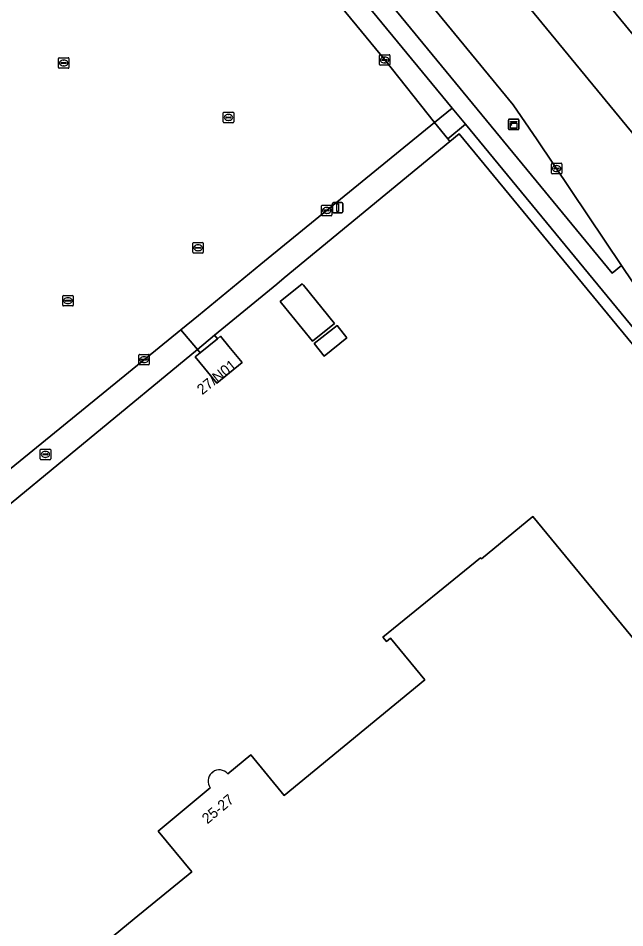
# Model space of a CAD drawing. Extents: x 156141 to 158132, y 385651 to 388333.
# Drawn here: x 157208.1 to 157265.8, y 386249.2 to 386335.6 of the extents above; entities that cross this region are included whole.
import ezdxf

# ---------------------------------------------------------------- set-up
doc = ezdxf.new("R2010")
doc.units = 0
for name, color, linetype in [('IMGEO_Berm_groen', 7, 'Continuous'), ('IMGEO_Brandkraan', 7, 'Continuous'), ('IMGEO_Erf', 7, 'Continuous'), ('IMGEO_Groenvoorziening', 7, 'Continuous'), ('IMGEO_Haag', 7, 'Continuous'), ('IMGEO_Hek', 7, 'Continuous'), ('IMGEO_Kast', 7, 'Continuous'), ('IMGEO_Kolk', 7, 'Continuous'), ('IMGEO_Lichtmast', 7, 'Continuous'), ('IMGEO_Pand', 7, 'Continuous'), ('IMGEO_Pand_nummerreeks', 7, 'Continuous'), ('IMGEO_Rijbaan_lokaal_gesloten', 7, 'Continuous'), ('IMGEO_Rioolput', 7, 'Continuous'), ('IMGEO_Voetpad_open', 7, 'Continuous')]:
    doc.layers.add(name, color=color, linetype=linetype)

msp = doc.modelspace()

# ---------------------------------------------------------------- linework, layer by layer
at = {"layer": 'IMGEO_Berm_groen'}
for points in [[(157205.755, 386407.826), (157203.781, 386410.196), (157199.193, 386406.39), (157201.153, 386404.033), (157327.942, 386250), (157336.115, 386240.102), (157337.285, 386238.671)], [(157342.288, 386241.546), (157341.401, 386242.711), (157335.682, 386250), (157205.755, 386407.826)], [(157211.154, 386376.22), (157264.546, 386311.336), (157265.451, 386312.065), (157257.428, 386324.032), (157255.15, 386327.344), (157194.1, 386401.515)]]:
    msp.add_lwpolyline(points, dxfattribs=at)
at = {"layer": 'IMGEO_Brandkraan'}
for p, q in [((157210.172, 386293.707), (157210.172, 386294.559)), ((157210.247, 386294.633), (157211.099, 386294.633)), ((157210.66, 386294.413), (157210.685, 386294.413)), ((157211.173, 386294.559), (157211.173, 386293.707)), ((157211.099, 386293.633), (157210.247, 386293.633)), ((157210.431, 386294.127), (157210.431, 386294.139)), ((157210.869, 386294.09), (157210.471, 386294.09)), ((157210.474, 386294.176), (157210.872, 386294.176)), ((157210.683, 386293.853), (157210.658, 386293.853)), ((157210.915, 386294.139), (157210.915, 386294.127))]:
    msp.add_line(p, q, dxfattribs=at)
for points in [[(157210.172, 386293.707), (157210.172, 386294.559)], [(157210.247, 386294.633), (157211.099, 386294.633)], [(157211.173, 386294.559), (157211.173, 386293.707)], [(157211.099, 386293.633), (157210.247, 386293.633)]]:
    msp.add_lwpolyline(points, dxfattribs=at)
for centre, radius, start, end in [((157210.249, 386294.557), 0.0765, 91.55205, 178.44795), ((157210.249, 386294.557), 0.0765, 91.55205, 178.44795), ((157211.097, 386294.557), 0.0765, 1.55205, 88.44795), ((157211.097, 386294.557), 0.0765, 1.55205, 88.44795), ((157210.249, 386293.709), 0.0765, 181.55205, 268.44795), ((157210.249, 386293.709), 0.0765, 181.55205, 268.44795), ((157210.471, 386294.136), 0.0403, 85.87752, 175.75265), ((157210.468, 386294.126), 0.0366, 178.93798, 274.71019), ((157210.872, 386294.133), 0.043, 264.86636, 352.45326), ((157210.876, 386294.138), 0.0386, 1.73085, 96.63898), ((157211.097, 386293.709), 0.0765, 271.55205, 358.44795), ((157211.097, 386293.709), 0.0765, 271.55205, 358.44795)]:
    msp.add_arc(centre, radius, start, end, dxfattribs=at)
for centre, major_axis, ratio, start_param, end_param in [((157210.659, 386294.133), (-0.387, 0.002), 0.722429, 4.712389, 7.853982), ((157210.684, 386294.133), (-0.39, 0.002), 0.717154, 1.570796, 4.712389)]:
    msp.add_ellipse(centre, major_axis=major_axis, ratio=ratio, start_param=start_param, end_param=end_param, dxfattribs=at)
at = {"layer": 'IMGEO_Erf'}
for points in [[(157223.541, 386305.983), (157225.229, 386307.333), (157231.137, 386312.191), (157231.851, 386312.773), (157247.676, 386325.673), (157242.926, 386331.607), (157204.09, 386378.741)], [(157213.671, 386179.31), (157318.008, 386237.675), (157310.24, 386250.894), (157308.881, 386253.009), (157305.737, 386257.034), (157297.068, 386267.539), (157250.016, 386324.597), (157249.125, 386323.863), (157233.385, 386310.904), (157232.673, 386310.318), (157226.757, 386305.447), (157227.019, 386305.124), (157227.309, 386305.361), (157228.122, 386304.37), (157229.365, 386302.857), (157226.965, 386300.89), (157224.909, 386303.4), (157225.394, 386303.796), (157225.13, 386304.108), (157163.286, 386253.19), (157161.441, 386255.415), (157161.905, 386255.778), (157223.541, 386305.983)], [(157252.024, 386284.317), (157252.119, 386284.201), (157257.025, 386288.239), (157288.502, 386250), (157288.753, 386249.695), (157266.104, 386236.815), (157262.283, 386243.437), (157254.077, 386236.659), (157255.229, 386235.26), (157246.303, 386227.923), (157245.155, 386229.365), (157210.228, 386200.571), (157189.567, 386225.684), (157219.124, 386250), (157224.577, 386254.486), (157221.379, 386258.33), (157226.345, 386262.461)], [(157228.013, 386263.798), (157230.205, 386265.602), (157233.383, 386261.742), (157246.732, 386272.73), (157243.491, 386276.668), (157243.105, 386276.35), (157242.755, 386276.774), (157252.024, 386284.317)], [(157226.478, 386263.873), (157226.574, 386263.953)]]:
    msp.add_lwpolyline(points, dxfattribs=at)
for points in [[(157233.128, 386308.491), (157232.999, 386308.65), (157235.084, 386310.349), (157235.204, 386310.201), (157238.154, 386306.582), (157236.069, 386304.883)], [(157238.407, 386306.377), (157239.339, 386305.198), (157237.159, 386303.475), (157236.227, 386304.654)]]:
    msp.add_lwpolyline(points, close=True, dxfattribs=at)
for centre, radius, start, end in [((157227.209, 386263.089), 1.072, 41.38761, 126.31671), ((157227.209, 386263.092), 1.07, 133.11872, 216.11935)]:
    msp.add_arc(centre, radius, start, end, dxfattribs=at)
at = {"layer": 'IMGEO_Groenvoorziening'}
msp.add_lwpolyline([(157204.09, 386378.741), (157242.926, 386331.607), (157247.676, 386325.673), (157249.344, 386327.032), (157209.826, 386374.969)], dxfattribs=at)
for points in [[(157250.614, 386325.491), (157248.932, 386324.105), (157249.125, 386323.863), (157250.016, 386324.597), (157297.068, 386267.539), (157305.737, 386257.034), (157308.881, 386253.009), (157310.24, 386250.894), (157318.008, 386237.675), (157319.091, 386238.264), (157310.849, 386252.423)], [(157223.541, 386305.983), (157161.905, 386255.778), (157161.441, 386255.415), (157163.286, 386253.19), (157225.13, 386304.108)]]:
    msp.add_lwpolyline(points, close=True, dxfattribs=at)
at = {"layer": 'IMGEO_Haag'}
msp.add_lwpolyline([(157223.541, 386305.983), (157161.905, 386255.778), (157161.441, 386255.415), (157163.286, 386253.19), (157225.13, 386304.108)], close=True, dxfattribs=at)
at = {"layer": 'IMGEO_Hek'}
for points in [[(157297.068, 386267.539), (157250.016, 386324.597), (157233.385, 386310.904)], [(157233.385, 386310.904), (157232.673, 386310.318)], [(157232.673, 386310.318), (157226.757, 386305.447)], [(157226.757, 386305.447), (157225.13, 386304.108)], [(157225.13, 386304.108), (157163.286, 386253.19)]]:
    msp.add_lwpolyline(points, dxfattribs=at)
at = {"layer": 'IMGEO_Kast'}
for p, q in [((157254.691, 386325.06), (157254.691, 386325.901)), ((157254.691, 386325.901), (157254.691, 386325.06)), ((157254.766, 386325.985), (157255.607, 386325.985)), ((157255.607, 386325.985), (157254.766, 386325.985)), ((157255.691, 386325.91), (157255.691, 386325.069)), ((157255.691, 386325.069), (157255.691, 386325.91)), ((157255.616, 386324.985), (157254.775, 386324.985)), ((157254.775, 386324.985), (157255.616, 386324.985))]:
    msp.add_line(p, q, dxfattribs=at)
for points in [[(157254.886, 386325.775), (157255.486, 386325.775), (157255.486, 386325.69), (157254.886, 386325.69), (157254.886, 386325.775)], [(157254.886, 386325.6), (157255.486, 386325.6), (157255.486, 386325.111), (157254.886, 386325.111), (157254.886, 386325.6)]]:
    msp.add_lwpolyline(points, dxfattribs=at)
msp.add_circle((157254.97, 386325.449), 0.0377, dxfattribs=at)
for centre, start, end in [((157254.769, 386325.907), 92.4484, 184.28452), ((157254.769, 386325.907), 92.4484, 184.28452), ((157255.613, 386325.907), 2.4484, 94.28452), ((157255.613, 386325.907), 2.4484, 94.28452), ((157254.769, 386325.063), 182.4484, 274.28452), ((157254.769, 386325.063), 182.4484, 274.28452), ((157255.613, 386325.063), 272.4484, 4.28452), ((157255.613, 386325.063), 272.4484, 4.28452)]:
    msp.add_arc(centre, 0.0779, start, end, dxfattribs=at)
at = {"layer": 'IMGEO_Kolk'}
for p, q in [((157211.911, 386330.892), (157211.911, 386331.744)), ((157211.986, 386331.818), (157212.838, 386331.818)), ((157212.399, 386331.598), (157212.424, 386331.598)), ((157212.912, 386331.744), (157212.912, 386330.892)), ((157242.425, 386331.181), (157242.425, 386332.033)), ((157242.5, 386332.107), (157243.352, 386332.107)), ((157242.684, 386331.601), (157242.684, 386331.613)), ((157243.122, 386331.564), (157242.724, 386331.564)), ((157242.727, 386331.65), (157243.125, 386331.65)), ((157242.913, 386331.887), (157242.938, 386331.887)), ((157243.168, 386331.613), (157243.168, 386331.601)), ((157243.426, 386332.033), (157243.426, 386331.181)), ((157212.838, 386330.818), (157211.986, 386330.818)), ((157212.17, 386331.312), (157212.17, 386331.324)), ((157212.608, 386331.275), (157212.21, 386331.275)), ((157212.213, 386331.361), (157212.611, 386331.361)), ((157212.422, 386331.038), (157212.397, 386331.038)), ((157212.654, 386331.324), (157212.654, 386331.312)), ((157243.352, 386331.107), (157242.5, 386331.107)), ((157242.936, 386331.327), (157242.911, 386331.327)), ((157227.574, 386325.716), (157227.574, 386326.568)), ((157227.649, 386326.642), (157228.501, 386326.642)), ((157228.062, 386326.422), (157228.087, 386326.422)), ((157228.575, 386326.568), (157228.575, 386325.716)), ((157228.501, 386325.642), (157227.649, 386325.642)), ((157227.833, 386326.136), (157227.833, 386326.148)), ((157228.271, 386326.099), (157227.873, 386326.099)), ((157227.876, 386326.185), (157228.274, 386326.185)), ((157228.085, 386325.862), (157228.06, 386325.862)), ((157228.317, 386326.148), (157228.317, 386326.136)), ((157258.775, 386320.865), (157258.775, 386321.717)), ((157258.85, 386321.791), (157259.702, 386321.791)), ((157259.034, 386321.285), (157259.034, 386321.297)), ((157259.472, 386321.248), (157259.074, 386321.248)), ((157259.077, 386321.334), (157259.475, 386321.334)), ((157259.263, 386321.571), (157259.288, 386321.571)), ((157259.518, 386321.297), (157259.518, 386321.285)), ((157259.776, 386321.717), (157259.776, 386320.865)), ((157259.702, 386320.791), (157258.85, 386320.791)), ((157259.286, 386321.011), (157259.261, 386321.011)), ((157236.915, 386316.884), (157236.915, 386317.736)), ((157236.99, 386317.81), (157237.842, 386317.81)), ((157237.916, 386317.736), (157237.916, 386316.884)), ((157237.842, 386316.81), (157236.99, 386316.81)), ((157237.174, 386317.304), (157237.174, 386317.316)), ((157237.612, 386317.267), (157237.214, 386317.267)), ((157237.217, 386317.353), (157237.615, 386317.353)), ((157237.426, 386317.03), (157237.401, 386317.03)), ((157237.403, 386317.59), (157237.428, 386317.59)), ((157237.658, 386317.316), (157237.658, 386317.304)), ((157212.315, 386308.308), (157212.315, 386309.16)), ((157212.39, 386309.234), (157213.242, 386309.234)), ((157212.803, 386309.014), (157212.828, 386309.014)), ((157213.316, 386309.16), (157213.316, 386308.308)), ((157213.242, 386308.234), (157212.39, 386308.234)), ((157212.574, 386308.728), (157212.574, 386308.74)), ((157213.012, 386308.691), (157212.614, 386308.691)), ((157212.617, 386308.777), (157213.015, 386308.777)), ((157212.826, 386308.454), (157212.801, 386308.454)), ((157213.058, 386308.74), (157213.058, 386308.728)), ((157219.548, 386302.712), (157219.548, 386303.564)), ((157219.623, 386303.638), (157220.475, 386303.638)), ((157219.807, 386303.132), (157219.807, 386303.144)), ((157220.245, 386303.095), (157219.847, 386303.095)), ((157219.85, 386303.181), (157220.248, 386303.181)), ((157220.036, 386303.418), (157220.061, 386303.418)), ((157220.291, 386303.144), (157220.291, 386303.132)), ((157220.549, 386303.564), (157220.549, 386302.712)), ((157220.475, 386302.638), (157219.623, 386302.638)), ((157220.059, 386302.858), (157220.034, 386302.858))]:
    msp.add_line(p, q, dxfattribs=at)
for points in [[(157211.911, 386330.892), (157211.911, 386331.744)], [(157211.986, 386331.818), (157212.838, 386331.818)], [(157212.912, 386331.744), (157212.912, 386330.892)], [(157242.425, 386331.181), (157242.425, 386332.033)], [(157242.5, 386332.107), (157243.352, 386332.107)], [(157243.426, 386332.033), (157243.426, 386331.181)], [(157212.838, 386330.818), (157211.986, 386330.818)], [(157243.352, 386331.107), (157242.5, 386331.107)], [(157227.574, 386325.716), (157227.574, 386326.568)], [(157227.649, 386326.642), (157228.501, 386326.642)], [(157228.575, 386326.568), (157228.575, 386325.716)], [(157228.501, 386325.642), (157227.649, 386325.642)], [(157258.775, 386320.865), (157258.775, 386321.717)], [(157258.85, 386321.791), (157259.702, 386321.791)], [(157259.776, 386321.717), (157259.776, 386320.865)], [(157259.702, 386320.791), (157258.85, 386320.791)], [(157236.915, 386316.884), (157236.915, 386317.736)], [(157236.99, 386317.81), (157237.842, 386317.81)], [(157237.916, 386317.736), (157237.916, 386316.884)], [(157237.842, 386316.81), (157236.99, 386316.81)], [(157212.315, 386308.308), (157212.315, 386309.16)], [(157212.39, 386309.234), (157213.242, 386309.234)], [(157213.316, 386309.16), (157213.316, 386308.308)], [(157213.242, 386308.234), (157212.39, 386308.234)], [(157219.548, 386302.712), (157219.548, 386303.564)], [(157219.623, 386303.638), (157220.475, 386303.638)], [(157220.549, 386303.564), (157220.549, 386302.712)], [(157220.475, 386302.638), (157219.623, 386302.638)]]:
    msp.add_lwpolyline(points, dxfattribs=at)
for centre, radius, start, end in [((157211.988, 386331.742), 0.0765, 91.55205, 178.44795), ((157211.988, 386331.742), 0.0765, 91.55205, 178.44795), ((157212.836, 386331.742), 0.0765, 1.55205, 88.44795), ((157212.836, 386331.742), 0.0765, 1.55205, 88.44795), ((157242.502, 386332.031), 0.0765, 91.55205, 178.44795), ((157242.502, 386332.031), 0.0765, 91.55205, 178.44795), ((157242.724, 386331.61), 0.0403, 85.87752, 175.75265), ((157242.721, 386331.6), 0.0366, 178.93798, 274.71019), ((157243.125, 386331.607), 0.043, 264.86636, 352.45326), ((157243.129, 386331.612), 0.0386, 1.73085, 96.63898), ((157243.35, 386332.031), 0.0765, 1.55205, 88.44795), ((157243.35, 386332.031), 0.0765, 1.55205, 88.44795), ((157211.988, 386330.894), 0.0765, 181.55205, 268.44795), ((157211.988, 386330.894), 0.0765, 181.55205, 268.44795), ((157212.21, 386331.321), 0.0403, 85.87752, 175.75265), ((157212.207, 386331.311), 0.0366, 178.93798, 274.71019), ((157212.611, 386331.318), 0.043, 264.86636, 352.45326), ((157212.615, 386331.323), 0.0386, 1.73085, 96.63898), ((157212.836, 386330.894), 0.0765, 271.55205, 358.44795), ((157212.836, 386330.894), 0.0765, 271.55205, 358.44795), ((157242.502, 386331.183), 0.0765, 181.55205, 268.44795), ((157242.502, 386331.183), 0.0765, 181.55205, 268.44795), ((157243.35, 386331.183), 0.0765, 271.55205, 358.44795), ((157243.35, 386331.183), 0.0765, 271.55205, 358.44795), ((157227.651, 386326.566), 0.0765, 91.55205, 178.44795), ((157227.651, 386326.566), 0.0765, 91.55205, 178.44795), ((157228.499, 386326.566), 0.0765, 1.55205, 88.44795), ((157228.499, 386326.566), 0.0765, 1.55205, 88.44795), ((157227.651, 386325.718), 0.0765, 181.55205, 268.44795), ((157227.651, 386325.718), 0.0765, 181.55205, 268.44795), ((157227.873, 386326.145), 0.0403, 85.87752, 175.75265), ((157227.87, 386326.135), 0.0366, 178.93798, 274.71019), ((157228.274, 386326.142), 0.043, 264.86636, 352.45326), ((157228.278, 386326.147), 0.0386, 1.73085, 96.63898), ((157228.499, 386325.718), 0.0765, 271.55205, 358.44795), ((157228.499, 386325.718), 0.0765, 271.55205, 358.44795), ((157258.852, 386321.715), 0.0765, 91.55205, 178.44795), ((157258.852, 386321.715), 0.0765, 91.55205, 178.44795), ((157259.074, 386321.294), 0.0403, 85.87752, 175.75265), ((157259.071, 386321.284), 0.0366, 178.93798, 274.71019), ((157259.475, 386321.291), 0.043, 264.86636, 352.45326), ((157259.479, 386321.296), 0.0386, 1.73085, 96.63898), ((157259.7, 386321.715), 0.0765, 1.55205, 88.44795), ((157259.7, 386321.715), 0.0765, 1.55205, 88.44795), ((157258.852, 386320.867), 0.0765, 181.55205, 268.44795), ((157258.852, 386320.867), 0.0765, 181.55205, 268.44795), ((157259.7, 386320.867), 0.0765, 271.55205, 358.44795), ((157259.7, 386320.867), 0.0765, 271.55205, 358.44795), ((157236.992, 386317.734), 0.0765, 91.55205, 178.44795), ((157236.992, 386317.734), 0.0765, 91.55205, 178.44795), ((157237.84, 386317.734), 0.0765, 1.55205, 88.44795), ((157237.84, 386317.734), 0.0765, 1.55205, 88.44795), ((157236.992, 386316.886), 0.0765, 181.55205, 268.44795), ((157236.992, 386316.886), 0.0765, 181.55205, 268.44795), ((157237.214, 386317.313), 0.0403, 85.87752, 175.75265), ((157237.211, 386317.303), 0.0366, 178.93798, 274.71019), ((157237.615, 386317.31), 0.043, 264.86636, 352.45326), ((157237.619, 386317.315), 0.0386, 1.73085, 96.63898), ((157237.84, 386316.886), 0.0765, 271.55205, 358.44795), ((157237.84, 386316.886), 0.0765, 271.55205, 358.44795), ((157212.392, 386309.158), 0.0765, 91.55205, 178.44795), ((157212.392, 386309.158), 0.0765, 91.55205, 178.44795), ((157213.24, 386309.158), 0.0765, 1.55205, 88.44795), ((157213.24, 386309.158), 0.0765, 1.55205, 88.44795), ((157212.392, 386308.31), 0.0765, 181.55205, 268.44795), ((157212.392, 386308.31), 0.0765, 181.55205, 268.44795), ((157212.614, 386308.737), 0.0403, 85.87752, 175.75265), ((157212.611, 386308.727), 0.0366, 178.93798, 274.71019), ((157213.015, 386308.734), 0.043, 264.86636, 352.45326), ((157213.019, 386308.739), 0.0386, 1.73085, 96.63898), ((157213.24, 386308.31), 0.0765, 271.55205, 358.44795), ((157213.24, 386308.31), 0.0765, 271.55205, 358.44795), ((157219.625, 386303.562), 0.0765, 91.55205, 178.44795), ((157219.625, 386303.562), 0.0765, 91.55205, 178.44795), ((157219.847, 386303.141), 0.0403, 85.87752, 175.75265), ((157219.844, 386303.131), 0.0366, 178.93798, 274.71019), ((157220.248, 386303.138), 0.043, 264.86636, 352.45326), ((157220.252, 386303.143), 0.0386, 1.73085, 96.63898), ((157220.473, 386303.562), 0.0765, 1.55205, 88.44795), ((157220.473, 386303.562), 0.0765, 1.55205, 88.44795), ((157219.625, 386302.714), 0.0765, 181.55205, 268.44795), ((157219.625, 386302.714), 0.0765, 181.55205, 268.44795), ((157220.473, 386302.714), 0.0765, 271.55205, 358.44795), ((157220.473, 386302.714), 0.0765, 271.55205, 358.44795)]:
    msp.add_arc(centre, radius, start, end, dxfattribs=at)
for centre, major_axis, ratio, start_param, end_param in [((157212.398, 386331.318), (-0.387, 0.002), 0.722429, 4.712389, 7.853982), ((157212.423, 386331.318), (-0.39, 0.002), 0.717154, 1.570796, 4.712389), ((157242.912, 386331.607), (-0.387, 0.002), 0.722429, 4.712389, 7.853982), ((157242.937, 386331.607), (-0.39, 0.002), 0.717154, 1.570796, 4.712389), ((157228.061, 386326.142), (-0.387, 0.002), 0.722429, 4.712389, 7.853982), ((157228.086, 386326.142), (-0.39, 0.002), 0.717154, 1.570796, 4.712389), ((157259.262, 386321.291), (-0.387, 0.002), 0.722429, 4.712389, 7.853982), ((157259.287, 386321.291), (-0.39, 0.002), 0.717154, 1.570796, 4.712389), ((157237.402, 386317.31), (-0.387, 0.002), 0.722429, 4.712389, 7.853982), ((157237.427, 386317.31), (-0.39, 0.002), 0.717154, 1.570796, 4.712389), ((157212.802, 386308.734), (-0.387, 0.002), 0.722429, 4.712389, 7.853982), ((157212.827, 386308.734), (-0.39, 0.002), 0.717154, 1.570796, 4.712389), ((157220.035, 386303.138), (-0.387, 0.002), 0.722429, 4.712389, 7.853982), ((157220.06, 386303.138), (-0.39, 0.002), 0.717154, 1.570796, 4.712389)]:
    msp.add_ellipse(centre, major_axis=major_axis, ratio=ratio, start_param=start_param, end_param=end_param, dxfattribs=at)
at = {"layer": 'IMGEO_Lichtmast'}
for p, q in [((157237.953, 386317.178), (157237.953, 386317.978)), ((157237.953, 386317.978), (157237.953, 386317.178)), ((157238.053, 386318.078), (157238.843, 386318.078)), ((157238.843, 386318.078), (157238.053, 386318.078)), ((157238.943, 386317.978), (157238.943, 386317.178)), ((157238.943, 386317.178), (157238.943, 386317.978)), ((157238.843, 386317.078), (157238.053, 386317.078)), ((157238.053, 386317.078), (157238.843, 386317.078))]:
    msp.add_line(p, q, dxfattribs=at)
msp.add_lwpolyline([(157238.373, 386317.953), (157238.523, 386317.953), (157238.523, 386317.203), (157238.373, 386317.203), (157238.373, 386317.953)], dxfattribs=at)
for centre, start, end in [((157238.053, 386317.978), 90, 180), ((157238.053, 386317.978), 90, 180), ((157238.843, 386317.978), 0, 90), ((157238.843, 386317.978), 360, 90), ((157238.053, 386317.178), 180, 270), ((157238.053, 386317.178), 180, 270), ((157238.843, 386317.178), 270, 0), ((157238.843, 386317.178), 270, 0)]:
    msp.add_arc(centre, 0.1, start, end, dxfattribs=at)
at = {"layer": 'IMGEO_Pand'}
for points in [[(157233.128, 386308.491), (157236.069, 386304.883), (157238.154, 386306.582), (157235.204, 386310.201), (157235.084, 386310.349), (157232.999, 386308.65)], [(157239.339, 386305.198), (157238.407, 386306.377), (157236.227, 386304.654), (157237.159, 386303.475)], [(157227.309, 386305.361), (157227.019, 386305.124), (157225.394, 386303.796), (157224.909, 386303.4), (157226.965, 386300.89), (157229.365, 386302.857), (157228.122, 386304.37)]]:
    msp.add_lwpolyline(points, close=True, dxfattribs=at)
for points in [[(157288.753, 386249.695), (157288.502, 386250), (157257.025, 386288.239), (157252.119, 386284.201), (157252.024, 386284.317), (157242.755, 386276.774), (157243.105, 386276.35), (157243.491, 386276.668), (157246.732, 386272.73), (157233.383, 386261.742), (157230.205, 386265.602), (157228.013, 386263.798)], [(157226.574, 386263.953), (157226.478, 386263.873)], [(157226.345, 386262.461), (157221.379, 386258.33), (157224.577, 386254.486), (157219.124, 386250), (157189.567, 386225.684), (157210.228, 386200.571), (157245.155, 386229.365), (157246.303, 386227.923), (157255.229, 386235.26), (157254.077, 386236.659), (157262.283, 386243.437), (157266.104, 386236.815), (157288.753, 386249.695)]]:
    msp.add_lwpolyline(points, dxfattribs=at)
for centre, radius, start, end in [((157227.209, 386263.089), 1.072, 41.38761, 126.31671), ((157227.209, 386263.092), 1.07, 133.11872, 216.11935)]:
    msp.add_arc(centre, radius, start, end, dxfattribs=at)
at = {"layer": 'IMGEO_Rijbaan_lokaal_gesloten'}
for points in [[(157200.977, 386413.621), (157203.099, 386411.016), (157203.781, 386410.196), (157205.755, 386407.826), (157335.682, 386250), (157341.401, 386242.711), (157342.288, 386241.546), (157344.37, 386238.82), (157346.391, 386236.066), (157355.377, 386240.641), (157355.147, 386240.882), (157352.86, 386243.28), (157351.407, 386244.818), (157349.349, 386247.071), (157349.183, 386247.253), (157332.608, 386264.801), (157324.262, 386275.047), (157320.799, 386279.156), (157212.168, 386411.116), (157210.786, 386412.789), (157209.596, 386414.647), (157209.078, 386415.949)], [(157327.507, 386224.107), (157341.674, 386233.351), (157339.581, 386235.895), (157339.51, 386235.998), (157337.285, 386238.671), (157336.115, 386240.102), (157327.942, 386250), (157201.153, 386404.033)], [(157192.877, 386402.642), (157194.1, 386401.515), (157255.15, 386327.344), (157257.428, 386324.032), (157265.451, 386312.065), (157270.545, 386304.503), (157271.759, 386302.908), (157316.481, 386248.624), (157325.045, 386238.218)]]:
    msp.add_lwpolyline(points, dxfattribs=at)
at = {"layer": 'IMGEO_Rioolput'}
for p, q in [((157224.755, 386314.26), (157225.607, 386314.26)), ((157224.68, 386313.334), (157224.68, 386314.186)), ((157224.939, 386313.754), (157224.939, 386313.766)), ((157225.377, 386313.717), (157224.979, 386313.717)), ((157224.982, 386313.803), (157225.38, 386313.803)), ((157225.191, 386313.48), (157225.166, 386313.48)), ((157225.168, 386314.04), (157225.193, 386314.04)), ((157225.423, 386313.766), (157225.423, 386313.754)), ((157225.681, 386314.186), (157225.681, 386313.334)), ((157225.607, 386313.26), (157224.755, 386313.26))]:
    msp.add_line(p, q, dxfattribs=at)
for points in [[(157224.755, 386314.26), (157225.607, 386314.26)], [(157224.68, 386313.334), (157224.68, 386314.186)], [(157225.681, 386314.186), (157225.681, 386313.334)], [(157225.607, 386313.26), (157224.755, 386313.26)]]:
    msp.add_lwpolyline(points, dxfattribs=at)
for centre, radius, start, end in [((157224.757, 386314.184), 0.0765, 91.55205, 178.44795), ((157224.757, 386314.184), 0.0765, 91.55205, 178.44795), ((157225.605, 386314.184), 0.0765, 1.55205, 88.44795), ((157225.605, 386314.184), 0.0765, 1.55205, 88.44795), ((157224.757, 386313.336), 0.0765, 181.55205, 268.44795), ((157224.757, 386313.336), 0.0765, 181.55205, 268.44795), ((157224.979, 386313.763), 0.0403, 85.87752, 175.75265), ((157224.976, 386313.753), 0.0366, 178.93798, 274.71019), ((157225.38, 386313.76), 0.043, 264.86636, 352.45326), ((157225.384, 386313.765), 0.0386, 1.73085, 96.63898), ((157225.605, 386313.336), 0.0765, 271.55205, 358.44795), ((157225.605, 386313.336), 0.0765, 271.55205, 358.44795)]:
    msp.add_arc(centre, radius, start, end, dxfattribs=at)
for centre, major_axis, ratio, start_param, end_param in [((157225.167, 386313.76), (-0.387, 0.002), 0.722429, 4.712389, 7.853982), ((157225.192, 386313.76), (-0.39, 0.002), 0.717154, 1.570796, 4.712389)]:
    msp.add_ellipse(centre, major_axis=major_axis, ratio=ratio, start_param=start_param, end_param=end_param, dxfattribs=at)
at = {"layer": 'IMGEO_Voetpad_open'}
for points in [[(157325.045, 386238.218), (157322.521, 386236.083), (157315.535, 386247.907), (157316.481, 386248.624), (157271.759, 386302.908), (157270.545, 386304.503), (157265.451, 386312.065), (157264.546, 386311.336), (157211.154, 386376.22)], [(157209.826, 386374.969), (157249.344, 386327.032), (157250.614, 386325.491), (157310.849, 386252.423), (157319.091, 386238.264), (157322.186, 386232.946), (157323.219, 386231.171)]]:
    msp.add_lwpolyline(points, dxfattribs=at)
for points in [[(157249.344, 386327.032), (157247.676, 386325.673), (157248.932, 386324.105), (157250.614, 386325.491)], [(157249.125, 386323.863), (157248.932, 386324.105), (157247.676, 386325.673), (157231.851, 386312.773), (157231.137, 386312.191), (157225.229, 386307.333), (157223.541, 386305.983), (157225.13, 386304.108), (157226.757, 386305.447), (157232.673, 386310.318), (157233.385, 386310.904)], [(157226.757, 386305.447), (157225.13, 386304.108), (157225.394, 386303.796), (157227.019, 386305.124)]]:
    msp.add_lwpolyline(points, close=True, dxfattribs=at)

# ---------------------------------------------------------------- texts
at = {"layer": 'IMGEO_Pand_nummerreeks'}
for s, rotation, p in [('27/N01', 38.55458, (157225.576, 386299.747)), ('25-27', 39.75754, (157226.07, 386258.98))]:
    msp.add_text(s, height=1, rotation=rotation, dxfattribs=at).set_placement(p)

doc.saveas('drawing.dxf')
